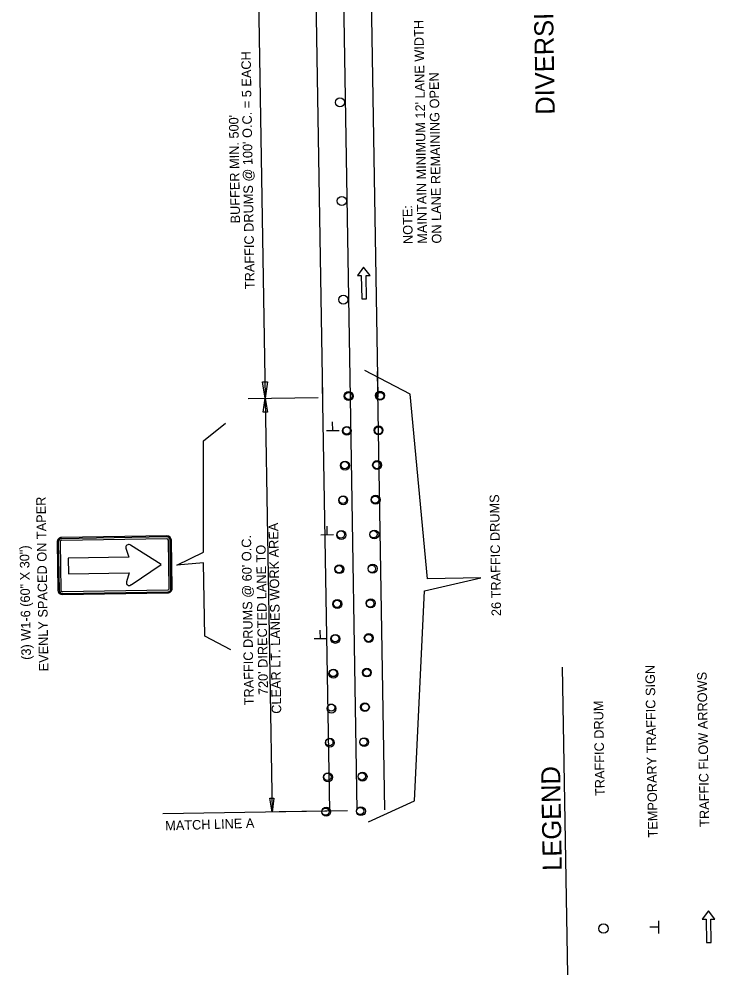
# Model space of a CAD drawing. Extents: x 1676639 to 1677883, y 226447 to 231777.
# Drawn here: x 1677429 to 1677868, y 228378 to 228980 of the extents above; entities that cross this region are included whole.
import ezdxf

# ---------------------------------------------------------------- set-up
doc = ezdxf.new("R2010")
doc.units = 0
for name, color, linetype in [('Default', 7, 'Continuous'), ('P_TC_Signs_Permanent', 7, 'Continuous'), ('R_Annotation', 7, 'Continuous'), ('R_MOT', 7, 'Continuous')]:
    doc.layers.add(name, color=color, linetype=linetype)

msp = doc.modelspace()

# ---------------------------------------------------------------- linework, layer by layer
at = {"layer": 'Default'}
for p, q in [((1677579.38, 229050.18), (1677584.5, 228741.12)), ((1677655.64, 228742.08), (1677651.08, 229017.11)), ((1677638.27, 228741.31), (1677633.76, 229013.27)), ((1677620.87, 228741.91), (1677616.41, 229010.81)), ((1677642.57, 228481.46), (1677638.05, 228754.24)), ((1677659.96, 228481.75), (1677655.38, 228757.95)), ((1677582.79, 228751.39), (1677585.88, 228751.45)), ((1677584.5, 228741.12), (1677582.79, 228751.39)), ((1677585.88, 228751.45), (1677584.5, 228741.12)), ((1677625.19, 228481.17), (1677620.73, 228750.19)), ((1677573.72, 228740.94), (1677618, 228741.67)), ((1677583.34, 228732.41), (1677584.5, 228741.12)), ((1677584.5, 228741.12), (1677588.83, 228480.38)), ((1677584.5, 228741.12), (1677585.95, 228732.45)), ((1677585.95, 228732.45), (1677583.34, 228732.41)), ((1677627.07, 228720.73), (1677626.98, 228726.18)), ((1677631.04, 228720.68), (1677623.06, 228720.55)), ((1677623.64, 228655.1), (1677623.55, 228660.55)), ((1677627.61, 228655.05), (1677619.63, 228654.92)), ((1677623.28, 228589.56), (1677615.3, 228589.43)), ((1677619.31, 228589.61), (1677619.22, 228595.06)), ((1677587.38, 228489.05), (1677589.99, 228489.09)), ((1677588.83, 228480.38), (1677587.38, 228489.05)), ((1677589.99, 228489.09), (1677588.83, 228480.38)), ((1677520.06, 228479.43), (1677636.32, 228481.36)), ((1677593.27, 228480.65), (1677636.32, 228481.36))]:
    msp.add_line(p, q, dxfattribs=at)
msp.add_lwpolyline([(1677649.55, 228474.23), (1677678.52, 228487.35), (1677684.8, 228619.75), (1677720.42, 228627.86), (1677686.86, 228627.31), (1677675.9, 228743.63), (1677647.31, 228758.7)], dxfattribs=at)
for centre, radius in [((1677631.59, 228927.56), 2.87), ((1677632.82, 228865.43), 2.87), ((1677633.71, 228803.3), 2.87), ((1677637.14, 228742.49), 2.81), ((1677637.06, 228742.5), 2.29), ((1677637.07, 228742.63), 2.29), ((1677656.81, 228742.82), 2.81), ((1677656.97, 228742.61), 2.29), ((1677656.96, 228742.49), 2.29), ((1677635.98, 228720.6), 2.81), ((1677635.85, 228720.8), 2.29), ((1677655.92, 228720.93), 2.81), ((1677655.92, 228720.81), 2.29), ((1677634.82, 228698.71), 2.81), ((1677634.64, 228698.97), 2.29), ((1677655.04, 228699.04), 2.81), ((1677654.87, 228699.02), 2.29), ((1677654.16, 228677.15), 2.81), ((1677633.66, 228676.81), 2.81), ((1677633.42, 228677.14), 2.29), ((1677653.82, 228677.22), 2.29), ((1677632.5, 228654.92), 2.81), ((1677632.21, 228655.31), 2.29), ((1677653.27, 228655.27), 2.81), ((1677652.78, 228655.42), 2.29), ((1677631.2, 228633.41), 2.81), ((1677631, 228633.48), 2.29), ((1677652.25, 228633.76), 2.81), ((1677651.73, 228633.62), 2.29), ((1677629.97, 228611.45), 2.81), ((1677629.78, 228611.65), 2.29), ((1677651.02, 228611.94), 2.81), ((1677650.68, 228611.82), 2.29), ((1677628.74, 228589.49), 2.81), ((1677628.57, 228589.82), 2.29), ((1677649.79, 228590.11), 2.81), ((1677649.63, 228590.02), 2.29), ((1677627.51, 228567.52), 2.81), ((1677627.35, 228567.99), 2.29), ((1677648.56, 228568.29), 2.81), ((1677648.58, 228568.23), 2.29), ((1677626.28, 228545.56), 2.81), ((1677626.14, 228546.16), 2.29), ((1677647.33, 228546.46), 2.81), ((1677647.53, 228546.43), 2.29), ((1677625.27, 228524.06), 2.81), ((1677624.93, 228524.33), 2.29), ((1677646.88, 228524.42), 2.81), ((1677646.48, 228524.63), 2.29), ((1677624.11, 228502.3), 2.81), ((1677645.86, 228502.67), 2.81), ((1677645.44, 228502.83), 2.29), ((1677623.71, 228502.5), 2.29), ((1677622.95, 228480.55), 2.81), ((1677622.49, 228480.54), 2.29), ((1677622.5, 228480.67), 2.29), ((1677644.83, 228480.91), 2.81), ((1677644.38, 228480.91), 2.29), ((1677644.39, 228481.03), 2.29), ((1677797.66, 228406.96), 3)]:
    msp.add_circle(centre, radius, dxfattribs=at)
at = {"layer": 'P_TC_Signs_Permanent'}
for p, q in [((1677453.42, 228650.51), (1677453.92, 228620.14)), ((1677454.17, 228650.52), (1677454.67, 228620.15)), ((1677455.29, 228650.54), (1677455.8, 228620.17)), ((1677522.55, 228654.47), (1677456.18, 228653.37)), ((1677522.56, 228653.72), (1677456.2, 228652.62)), ((1677522.58, 228652.59), (1677456.21, 228651.49)), ((1677524.04, 228621.3), (1677523.53, 228651.67)), ((1677525.16, 228621.32), (1677524.66, 228651.69)), ((1677525.91, 228621.33), (1677525.41, 228651.7)), ((1677456.75, 228619.25), (1677523.11, 228620.35)), ((1677456.77, 228618.12), (1677523.13, 228619.22)), ((1677456.78, 228617.37), (1677523.15, 228618.47))]:
    msp.add_line(p, q, dxfattribs=at)
for points in [[(1677496.78, 228646.67), (1677498.6, 228640.94), (1677460.34, 228640.31), (1677460.5, 228630.56), (1677498.76, 228631.19), (1677497.1, 228625.42)], [(1677500.13, 228623.65), (1677518.91, 228636.4), (1677499.7, 228648.5)]]:
    msp.add_lwpolyline(points, dxfattribs=at)
for centre, radius, start, end in [((1677456.23, 228650.55), 2.81, 90.94971, 180.94971), ((1677456.23, 228650.55), 2.06, 90.94971, 180.94971), ((1677456.23, 228650.55), 0.937, 90.94971, 180.94971), ((1677522.6, 228651.65), 2.81, 0.94971, 90.94971), ((1677522.6, 228651.65), 2.06, 0.94971, 90.94971), ((1677522.6, 228651.65), 0.938, 0.94971, 90.94971), ((1677498.47, 228647.19), 1.76, 57.54915, 196.91879), ((1677539.66, 228711.96), 75, 237.54915, 237.80668), ((1677456.73, 228620.18), 2.81, 180.94971, 270.94971), ((1677456.73, 228620.18), 2.06, 180.94971, 270.94971), ((1677456.73, 228620.18), 0.938, 180.94971, 270.94971), ((1677498.84, 228624.95), 1.8, 164.98064, 304.42519), ((1677542.26, 228561.6), 75, 124.17831, 124.42519), ((1677523.1, 228621.28), 0.938, 270.94971, 0.94971), ((1677523.1, 228621.28), 2.06, 270.94971, 0.94971), ((1677523.1, 228621.28), 2.81, 270.94971, 0.94971)]:
    msp.add_arc(centre, radius, start, end, dxfattribs=at)
at = {"layer": 'R_Annotation'}
for p, q in [((1677775.25, 228377.77), (1677771.91, 228571.66)), ((1677832.28, 228411.89), (1677832.42, 228403.89)), ((1677832.23, 228407.91), (1677826.78, 228407.82))]:
    msp.add_line(p, q, dxfattribs=at)
msp.add_lwpolyline([(1677650.58, 228818.51), (1677646.49, 228823.63), (1677642.58, 228818.37), (1677645.08, 228818.41), (1677645.33, 228803.7), (1677648.33, 228803.75), (1677648.08, 228818.46)], close=True, dxfattribs=at)
msp.add_lwpolyline([(1677562.96, 228582.51), (1677546.51, 228591.25), (1677545.74, 228637.47), (1677528.88, 228635.99), (1677545.63, 228644.07), (1677545.63, 228714.33), (1677559.43, 228725.37)], dxfattribs=at)
at = {"layer": 'R_MOT'}
msp.add_lwpolyline([(1677867.85, 228412.98), (1677863.76, 228418.1), (1677859.85, 228412.84), (1677862.35, 228412.88), (1677862.6, 228398.17), (1677865.6, 228398.22), (1677865.35, 228412.93)], close=True, dxfattribs=at)

# ---------------------------------------------------------------- texts
at = {"layer": 'Default'}
msp.add_text('DIVERSION FOR LT. LANE WORK ZONE', height=12, rotation=90.94971, dxfattribs=at).set_placement((1677767, 228919.9))
at = {"layer": 'R_Annotation'}
for s, height, rotation, p in [("MAINTAIN MINIMUM 12' LANE WIDTH", 6, 90.94971, (1677686.56, 228838.51)), ("TRAFFIC DRUMS @ 100' O.C. = 5 EACH", 6, 90.94971, (1677577.86, 228809.94)), ('ON LANE REMAINING OPEN', 6, 90.94971, (1677695.6, 228838.66)), ("BUFFER MIN. 500'", 6, 90.94971, (1677568.74, 228851.34)), ('NOTE:', 6, 90.94971, (1677677.51, 228838.36)), ('26 TRAFFIC DRUMS', 6, 90.94971, (1677733.15, 228603.93)), ('EVENLY SPACED ON TAPER', 6, 90.95726, (1677448.01, 228569.06)), ('CLEAR LT. LANES WORK AREA', 6, 90.94971, (1677594.66, 228542.36)), ("TRAFFIC DRUMS @ 60' O.C.", 6, 90.94971, (1677577.37, 228547.7)), ('(3) W1-6 (60" X 30")', 6, 90.95726, (1677436.97, 228576.34)), ("720' DIRECTED LANE TO", 6, 90.94971, (1677586.33, 228554.14)), ('TEMPORARY TRAFFIC SIGN', 6, 90.98847, (1677831.81, 228464.4)), ('TRAFFIC FLOW ARROWS', 6, 90.98847, (1677864.34, 228471.13)), ('TRAFFIC DRUM', 6, 90.98847, (1677798.47, 228490.52)), ('LEGEND', 12, 90.9885, (1677771.44, 228443.44)), ('MATCH LINE A', 6, 1.75564, (1677521.61, 228468.76))]:
    msp.add_text(s, height=height, rotation=rotation, dxfattribs=at).set_placement(p)

doc.saveas('drawing.dxf')
